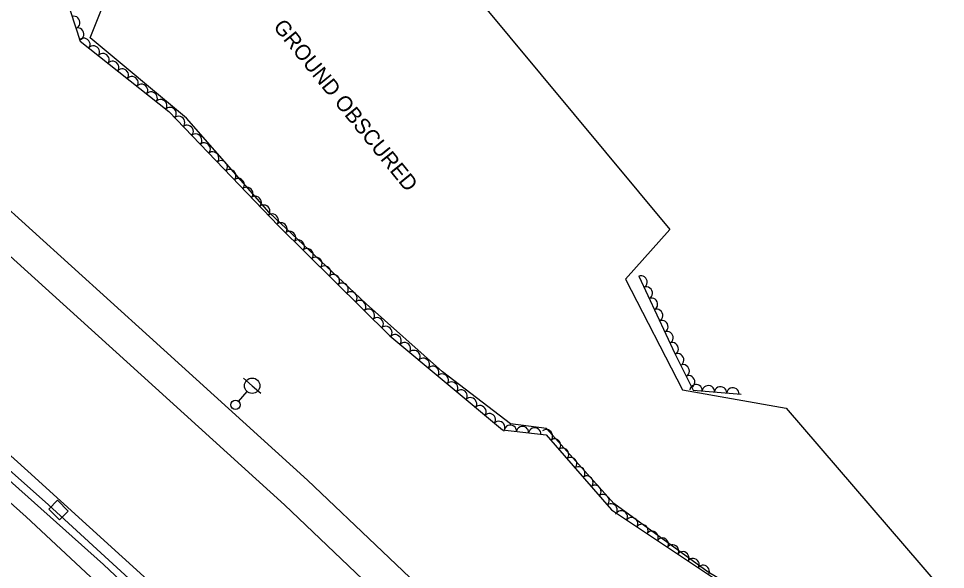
# Model space of a CAD drawing. Extents: x 1746719 to 1766531, y 631721 to 662391.
# Drawn here: x 1757419.3 to 1757720.6, y 645146 to 645325.3 of the extents above; entities that cross this region are included whole.
import ezdxf

# ---------------------------------------------------------------- set-up
doc = ezdxf.new("R2010")
doc.units = 0
for name, color, linetype in [('SURVEY - AERIAL SURVEY - Photo Control - Points - Elevations', 7, 'Continuous'), ('SURVEY - AERIAL SURVEY - Photo Control - Points - Locators', 7, 'Continuous'), ('SURVEY - AERIAL SURVEY - Photo Control - Points - Numbers', 7, 'Continuous'), ('SURVEY - AERIAL SURVEY - Photo Control with Text', 7, 'Continuous'), ('SURVEY - CENTERLINE - Existing Roads - Development', 7, 'Continuous'), ('SURVEY - CENTERLINE - Preliminary Curve Text', 7, 'Continuous')]:
    doc.layers.add(name, color=color, linetype=linetype)

msp = doc.modelspace()

# ---------------------------------------------------------------- linework, layer by layer
at = {"layer": 'SURVEY - AERIAL SURVEY - Photo Control - Points - Elevations'}
for points in [[(1757367.68, 645305.09), (1757410.99, 645267.65), (1757461.87, 645221.66), (1757513.21, 645175.01), (1757561.94, 645128.57), (1757616.86, 645075.81), (1757665.43, 645027.56), (1757715.64, 644976.79), (1757758.33, 644932.62), (1757807.87, 644879.88), (1757857.69, 644825.63), (1757895.55, 644783.99), (1757959.32, 644710.69), (1758018.17, 644640.98), (1758071.69, 644576.23), (1758126.48, 644507.24), (1758180.58, 644436.89), (1758227.03, 644375.61), (1758268.25, 644319.14), (1758280.54, 644301.89)], [(1757360.49, 645296.77), (1757403.7, 645259.41), (1757454.49, 645213.51), (1757505.72, 645166.96), (1757554.33, 645120.63), (1757609.17, 645067.94), (1757657.64, 645019.79), (1757707.77, 644969.1), (1757750.37, 644925.03), (1757799.81, 644872.39), (1757849.57, 644818.21), (1757887.33, 644776.67), (1757950.96, 644703.53), (1758009.72, 644633.92), (1758063.14, 644569.3), (1758117.82, 644500.46), (1758171.84, 644430.21), (1758218.21, 644369.05), (1758259.33, 644312.71), (1758271.58, 644295.51)], [(1757329.1, 645260.45), (1757371.91, 645223.45), (1757422.26, 645177.94), (1757473.01, 645131.82), (1757521.15, 645085.95), (1757575.62, 645033.61), (1757623.66, 644985.89), (1757673.45, 644935.54), (1757715.62, 644891.92), (1757764.64, 644839.73), (1757814.13, 644785.84), (1757851.46, 644744.78), (1757914.52, 644672.3), (1757972.89, 644603.15), (1758025.84, 644539.08), (1758079.99, 644470.91), (1758133.69, 644401.08), (1758179.69, 644340.39), (1758220.4, 644284.63), (1758232.48, 644267.66)], [(1757319.72, 645253.76), (1757362.56, 645216.07), (1757421.72, 645163.08), (1757476.45, 645112.02), (1757525.72, 645065.8), (1757571.85, 645021.26), (1757612.1, 644981.49), (1757656.02, 644937.25), (1757724.73, 644866.33), (1757766.64, 644821.42), (1757820.62, 644761.16), (1757859.7, 644717.48), (1757906.2, 644664.72), (1757956.17, 644605.79), (1757997.01, 644556.15), (1758046.25, 644495.62), (1758098.65, 644428.72), (1758149.56, 644361.05), (1758194.39, 644300.47), (1758220.54, 644263.88)]]:
    msp.add_lwpolyline(points, dxfattribs=at)
at = {"layer": 'SURVEY - AERIAL SURVEY - Photo Control - Points - Locators'}
for points in [[(1757526.95, 645381.86), (1757630.99, 645256.61), (1757616.57, 645240.48), (1757635.11, 645204.47), (1757668.81, 645198.47), (1757740.53, 645115.06), (1757793.62, 645062.46), (1757779.04, 645050.91), (1757809.3, 645018.73), (1757830.77, 645031.33), (1757896.9, 644966.26), (1757954.62, 644910.74), (1757990.29, 644874.82), (1758056.24, 644796.02), (1758129.7, 644716.01), (1758213.56, 644630.46), (1758277.65, 644559.78), (1758333.42, 644477.52), (1758378.47, 644411.27)], [(1758003.84, 644790.61), (1757972.55, 644825), (1757944.8, 644862.43), (1757922.32, 644886.65), (1757903.4, 644907.9), (1757875.82, 644937.41), (1757819.35, 644984.4), (1757766.85, 645029.13), (1757730.77, 645063.66), (1757683.2, 645109.02), (1757651.92, 645140.06), (1757643.47, 645145.12), (1757612.82, 645167.44), (1757590.91, 645191.82), (1757579.18, 645193.34), (1757557.13, 645210.26), (1757532.24, 645232.42), (1757500.7, 645262.18), (1757473.89, 645292.88), (1757442.57, 645318.98), (1757448.22, 645333.19)]]:
    msp.add_lwpolyline(points, dxfattribs=at)
at = {"layer": 'SURVEY - AERIAL SURVEY - Photo Control - Points - Numbers'}
for points in [[(1757323.62, 645256.72), (1757359.68, 645224.76), (1757401.86, 645187.77), (1757446.88, 645147.55), (1757499.98, 645097.49), (1757551.19, 645048.47), (1757597.89, 645002.53), (1757644.17, 644956.09), (1757689.91, 644909.35), (1757731.53, 644865.88), (1757784.85, 644808.61), (1757831.81, 644757.26), (1757876.31, 644706.72), (1757924.6, 644650.39), (1757975.41, 644590.54), (1758021.86, 644533.64), (1758061.14, 644483.77), (1758123.13, 644404.33), (1758167.18, 644346.13), (1758206.86, 644292.21), (1758240.55, 644244.25)], [(1757390.53, 645201.2), (1757429.02, 645166.95), (1757455.13, 645143.08), (1757484.39, 645115.95), (1757513.99, 645087.65), (1757545.18, 645057.29), (1757569.55, 645033.61), (1757589.29, 645014.47), (1757602.52, 645001.61), (1757625.87, 644977.97), (1757653.48, 644950.42), (1757678.89, 644924.58), (1757710.27, 644891.52), (1757738.12, 644862.04), (1757767.76, 644831.01), (1757798.81, 644797.43)]]:
    msp.add_lwpolyline(points, dxfattribs=at)
at = {"layer": 'SURVEY - AERIAL SURVEY - Photo Control with Text'}
for points in [[(1757433.01, 645337.36), (1757439.33, 645317.93), (1757468.08, 645295.01), (1757503.75, 645257.75), (1757539.98, 645221.98), (1757576.56, 645191.36), (1757590.81, 645189.74), (1757612.05, 645165.36), (1757650.79, 645139.53), (1757660.94, 645128.03), (1757698.87, 645092.06), (1757742.37, 645050.45), (1757774.84, 645019.97), (1757821.42, 644979.76), (1757871.76, 644936.92), (1757895.93, 644913.17), (1757940.01, 644864.35), (1757959.77, 644839.2), (1757982.2, 644810.7), (1758042.61, 644749.17)], [(1757620.94, 645241.4), (1757632.67, 645216.22), (1757638.61, 645204.35), (1757654.25, 645203)]]:
    msp.add_lwpolyline(points, dxfattribs=at)
for centre, major_axis in [((1757437.34, 645324.04), (0.62, -1.9)), ((1757438.58, 645320.24), (0.62, -1.9)), ((1757440.56, 645316.95), (1.56, -1.25)), ((1757443.69, 645314.46), (1.56, -1.25)), ((1757446.81, 645311.96), (1.56, -1.25)), ((1757449.94, 645309.47), (1.56, -1.25)), ((1757453.07, 645306.98), (1.56, -1.25)), ((1757456.2, 645304.48), (1.56, -1.25)), ((1757459.32, 645301.99), (1.56, -1.25)), ((1757462.45, 645299.49), (1.56, -1.25)), ((1757465.58, 645297), (1.56, -1.25)), ((1757468.63, 645294.43), (1.38, -1.44)), ((1757471.4, 645291.54), (1.38, -1.44)), ((1757474.16, 645288.65), (1.38, -1.44)), ((1757476.93, 645285.76), (1.38, -1.44)), ((1757479.7, 645282.87), (1.38, -1.44)), ((1757482.46, 645279.98), (1.38, -1.44)), ((1757485.23, 645277.09), (1.38, -1.44)), ((1757488, 645274.2), (1.38, -1.44)), ((1757490.76, 645271.31), (1.38, -1.44)), ((1757493.53, 645268.42), (1.38, -1.44)), ((1757496.29, 645265.53), (1.38, -1.44)), ((1757499.06, 645262.64), (1.38, -1.44)), ((1757501.83, 645259.75), (1.38, -1.44)), ((1757504.62, 645256.89), (1.42, -1.41)), ((1757507.46, 645254.08), (1.42, -1.41)), ((1757510.31, 645251.27), (1.42, -1.41)), ((1757513.16, 645248.46), (1.42, -1.41)), ((1757516, 645245.65), (1.42, -1.41)), ((1757518.85, 645242.84), (1.42, -1.41)), ((1757521.7, 645240.03), (1.42, -1.41)), ((1757621.78, 645239.58), (0.84, -1.81)), ((1757524.54, 645237.22), (1.42, -1.41)), ((1757623.47, 645235.96), (0.84, -1.81)), ((1757527.39, 645234.41), (1.42, -1.41)), ((1757530.24, 645231.6), (1.42, -1.41)), ((1757625.16, 645232.33), (0.84, -1.81)), ((1757533.08, 645228.79), (1.42, -1.41)), ((1757626.85, 645228.7), (0.84, -1.81)), ((1757535.93, 645225.98), (1.42, -1.41)), ((1757628.54, 645225.08), (0.84, -1.81)), ((1757538.78, 645223.17), (1.42, -1.41)), ((1757541.75, 645220.5), (1.53, -1.28)), ((1757630.23, 645221.45), (0.84, -1.81)), ((1757544.82, 645217.93), (1.53, -1.28)), ((1757631.92, 645217.83), (0.84, -1.81)), ((1757547.89, 645215.36), (1.53, -1.28)), ((1757550.95, 645212.8), (1.53, -1.28)), ((1757633.67, 645214.23), (0.9, -1.79)), ((1757554.02, 645210.23), (1.53, -1.28)), ((1757635.46, 645210.65), (0.9, -1.79)), ((1757557.09, 645207.66), (1.53, -1.28)), ((1757637.25, 645207.08), (0.9, -1.79)), ((1757560.16, 645205.09), (1.53, -1.28)), ((1757563.22, 645202.53), (1.53, -1.28)), ((1757639.56, 645204.27), (1.99, -0.17)), ((1757643.55, 645203.93), (1.99, -0.17)), ((1757647.53, 645203.58), (1.99, -0.17)), ((1757651.52, 645203.24), (1.99, -0.17)), ((1757566.29, 645199.96), (1.53, -1.28)), ((1757569.36, 645197.39), (1.53, -1.28)), ((1757572.42, 645194.82), (1.53, -1.28)), ((1757575.49, 645192.26), (1.53, -1.28)), ((1757579.15, 645191.07), (1.99, -0.23)), ((1757583.12, 645190.62), (1.99, -0.23)), ((1757587.1, 645190.17), (1.99, -0.23)), ((1757590.98, 645189.55), (1.31, -1.51)), ((1757593.61, 645186.53), (1.31, -1.51)), ((1757596.24, 645183.52), (1.31, -1.51)), ((1757598.87, 645180.5), (1.31, -1.51)), ((1757601.49, 645177.48), (1.31, -1.51)), ((1757604.12, 645174.47), (1.31, -1.51)), ((1757606.75, 645171.45), (1.31, -1.51)), ((1757609.38, 645168.44), (1.31, -1.51)), ((1757612.01, 645165.42), (1.31, -1.51)), ((1757615.32, 645163.19), (1.66, -1.11)), ((1757618.65, 645160.97), (1.66, -1.11)), ((1757621.98, 645158.75), (1.66, -1.11)), ((1757625.3, 645156.53), (1.66, -1.11)), ((1757628.63, 645154.31), (1.66, -1.11)), ((1757631.96, 645152.09), (1.66, -1.11)), ((1757635.29, 645149.87), (1.66, -1.11)), ((1757638.61, 645147.65), (1.66, -1.11)), ((1757641.94, 645145.43), (1.66, -1.11))]:
    msp.add_ellipse(centre, major_axis=major_axis, ratio=0.940188, start_param=0, end_param=3.141593, dxfattribs=at)
at = {"layer": 'SURVEY - CENTERLINE - Existing Roads - Development'}
for p, q in [((1757495.21, 645205.76), (1757492.39, 645208.23)), ((1757495.21, 645205.76), (1757498.04, 645203.3)), ((1757490.77, 645200.68), (1757493.57, 645203.88))]:
    msp.add_line(p, q, dxfattribs=at)
for centre, radius in [((1757495.21, 645205.76), 2.5), ((1757489.79, 645199.55), 1.5)]:
    msp.add_circle(centre, radius, dxfattribs=at)
at = {"layer": 'SURVEY - CENTERLINE - Preliminary Curve Text'}
msp.add_line((1757432.24, 645165.3), (1757432.24, 645165.3), dxfattribs=at)
msp.add_lwpolyline([(1757429.06, 645165.64), (1757431.88, 645168.48), (1757435.42, 645164.95), (1757432.6, 645162.12), (1757429.06, 645165.64)], dxfattribs=at)

# ---------------------------------------------------------------- texts
at = {"layer": 'SURVEY - AERIAL SURVEY - Photo Control - Points - Locators'}
msp.add_text('GROUND OBSCURED', height=5, rotation=309.0122, dxfattribs=at).set_placement((1757501.85, 645322.5))

doc.saveas('drawing.dxf')
